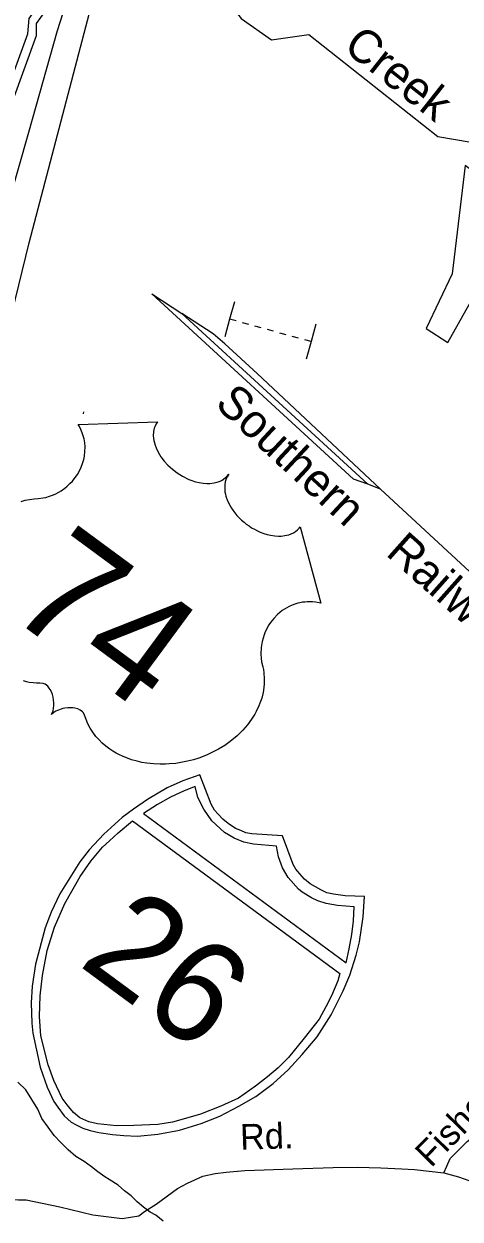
# Model space of a CAD drawing. Extents: x 945666 to 965748, y 644452 to 663300.
# Drawn here: x 952293 to 952548, y 658594 to 659294 of the extents above; entities that cross this region are included whole.
import ezdxf

# ---------------------------------------------------------------- set-up
doc = ezdxf.new("R2010")
doc.units = 0
for name, color, linetype in [('Exist Hydrographic Buffer Line', 7, 'Continuous'), ('Exist Hydrographic Creek Single Shore', 7, 'Continuous'), ('Exist Hydrographic Pond Under 1500 Sq Ft', 7, 'Continuous'), ('Exist Hydrographic River Shore', 7, 'Continuous'), ('Exist Railroad Mainline Label', 7, 'Continuous'), ('Exist Railroad Siding', 7, 'Continuous'), ('Exist Road Primary Interstate Divided Center Attributed', 7, 'Continuous'), ('Exist Road Primary Interstate Shield Number Label', 7, 'Continuous'), ('Exist Road Primary Interstate Structure Vehicle Undrpass CELL', 7, 'Continuous'), ('Exist Road Primary US Shield Number Label', 7, 'Continuous'), ('Exist Road Secondary Type 51 Attributed', 7, 'Continuous'), ('Exist Road Secondary Type 51 Label', 7, 'Continuous'), ('Prop Paved Shoulder', 7, 'Continuous'), ('Prop Shade Light', 7, 'Continuous'), ('Prop Terminator CELL', 7, 'Continuous'), ('Sheet Title CELL', 7, 'Continuous')]:
    doc.layers.add(name, color=color, linetype=linetype)

msp = doc.modelspace()

# ---------------------------------------------------------------- linework, layer by layer
at = {"layer": 'Exist Hydrographic Buffer Line'}
for points in [[(952295, 659288.27), (952295.93, 659297.32), (952305.44, 659310.93), (952312.26, 659335.51)], [(952184.88, 658621.35), (952177.44, 658687.19), (952181.39, 658753.39), (952195.29, 658856.25), (952214.9, 658982.47), (952235.87, 659046.83), (952242.36, 659117.47), (952249.52, 659158.51), (952261.34, 659195.91), (952295, 659288.27)]]:
    msp.add_lwpolyline(points, dxfattribs=at)
at = {"layer": 'Exist Hydrographic Creek Single Shore'}
for points in [[(952332.6, 659363.1), (952363.43, 659340.89), (952391.12, 659328.73), (952405.78, 659315.85), (952420.09, 659297.31), (952437.78, 659284.79), (952459.62, 659287.9), (952535.2, 659228.17), (952554.77, 659224.95), (952566.09, 659226.99)], [(952374.28, 658592.95), (952370.07, 658596.42), (952366.78, 658598.08), (952362.86, 658601.09), (952359.04, 658604.24), (952355.64, 658607.72), (952351.73, 658610.73), (952348.01, 658614.01), (952342.76, 658617.19), (952340.09, 658618.82), (952336.17, 658621.83), (952332.45, 658624.69), (952328.02, 658627.88), (952323.12, 658630.79), (952318.77, 658634.57), (952314.15, 658639.2), (952310.42, 658643.14), (952306.89, 658648), (952303.36, 658653.08), (952300.87, 658658.43), (952297.46, 658664.06), (952293.81, 658669.88), (952289.3, 658674.22)]]:
    msp.add_lwpolyline(points, dxfattribs=at)
at = {"layer": 'Exist Hydrographic Pond Under 1500 Sq Ft'}
msp.add_line((952327.59, 659065.82), (952327.87, 659066.92), dxfattribs=at)
msp.add_lwpolyline([(952541.15, 659107.46), (952561.6, 659143.99), (952563.9, 659201.58), (952551.33, 659211.25), (952543.67, 659147.67), (952528.48, 659115.69), (952541.15, 659107.46)], dxfattribs=at)
at = {"layer": 'Exist Hydrographic River Shore'}
msp.add_lwpolyline([(952190.58, 658617.15), (952182.63, 658686.88), (952186.54, 658752.7), (952200.43, 658855.45), (952219.84, 658980.86), (952240.98, 659045.77), (952247.49, 659116.59), (952254.31, 659156.5), (952268.31, 659189.83), (952266.21, 659194.13), (952300.2, 659287.35), (952300.19, 659294.35), (952310.21, 659308.69), (952320.45, 659345.96), (952321.5, 659348.05)], dxfattribs=at)
at = {"layer": 'Exist Railroad Siding'}
for p, q in [((952494.15, 659024.46), (952385.24, 659124.54)), ((952501.65, 659021.7), (952494.15, 659024.46)), ((952553.83, 658973.41), (952501.65, 659021.7))]:
    msp.add_line(p, q, dxfattribs=at)
for points in [[(952494.15, 659024.46), (952485.83, 659027.41), (952367.75, 659136.05), (952385.24, 659124.54)], [(952501.65, 659021.7), (952429.32, 659089.36), (952410.47, 659106.65), (952403.55, 659112.61), (952385.24, 659124.54)]]:
    msp.add_lwpolyline(points, dxfattribs=at)
at = {"layer": 'Exist Road Primary Interstate Divided Center Attributed'}
for points in [[(952218.29, 658596.72), (952220.44, 658613.7), (952228.12, 658689.95), (952243.24, 658837.53), (952254.14, 658963.62), (952258.26, 658998.75), (952267.23, 659049.19), (952295.78, 659165.98), (952342.48, 659343.91), (952356.23, 659395.14)], [(952336.65, 659368.59), (952330.58, 659347.56), (952312.18, 659290.03), (952295.46, 659230.61), (952272.27, 659149.42), (952256.21, 659087.83), (952244.09, 659032.36), (952239.92, 659005.62), (952235.48, 658965.71), (952215.32, 658767.01), (952200.36, 658609.94)]]:
    msp.add_lwpolyline(points, dxfattribs=at)
at = {"layer": 'Exist Road Primary Interstate Structure Vehicle Undrpass CELL'}
for p, q in [((952416.08, 659131.43), (952413.26, 659121.15)), ((952413.26, 659121.15), (952410.44, 659110.86)), ((952417.06, 659120.13), (952413.27, 659121.17)), ((952424.43, 659118.1), (952420.75, 659119.11)), ((952463.84, 659118.34), (952461.02, 659108.05)), ((952431.8, 659116.08), (952428.12, 659117.09)), ((952439.05, 659114.08), (952435.37, 659115.1)), ((952446.42, 659112.06), (952442.74, 659113.07)), ((952453.65, 659110.08), (952449.96, 659111.09)), ((952461.02, 659108.05), (952457.33, 659109.07)), ((952461.02, 659108.05), (952458.2, 659097.77))]:
    msp.add_line(p, q, dxfattribs=at)
at = {"layer": 'Exist Road Secondary Type 51 Attributed'}
for points in [[(952538.83, 658621.21), (952540.53, 658625.12), (952542.41, 658629.48), (952552.45, 658639.48), (952567.61, 658651.44), (952576.86, 658661.58), (952596.81, 658693.78), (952603.46, 658702.99), (952607.51, 658707.74)], [(952275.84, 658603.72), (952279.85, 658604.75), (952285.32, 658605.57), (952289.63, 658605.42), (952294.06, 658605.45), (952313.72, 658601.29), (952333.2, 658596.51), (952350.33, 658594.35), (952360.18, 658596.03), (952363.5, 658598.46), (952370.22, 658602.9), (952382.74, 658611.93), (952388.68, 658615.08), (952397.67, 658619.16), (952404.81, 658620.73), (952411.3, 658621.63), (952422.18, 658622.6), (952450.3, 658623.54), (952473.93, 658624.39), (952488.27, 658624.44), (952501.8, 658624.19), (952514.12, 658623.5), (952521.65, 658623.11), (952538.83, 658621.21)], [(952538.83, 658621.21), (952547.25, 658618.83), (952553.96, 658616.54), (952557.75, 658614.48), (952564.84, 658609.7), (952567.41, 658605.59), (952571.13, 658600.63), (952575.88, 658591.67), (952578.65, 658582.03), (952580.78, 658565.71), (952581.64, 658556.04), (952582.97, 658542.02), (952586.67, 658491.09), (952588.4, 658469.76), (952591.07, 658427.09), (952591.1, 658412.52), (952591.14, 658406.64), (952591.15, 658399.33), (952590.7, 658391.2), (952589.55, 658376.03), (952585.63, 658355.48), (952576.67, 658332.4)]]:
    msp.add_lwpolyline(points, dxfattribs=at)
at = {"layer": 'Prop Shade Light'}
for points in [[(952320.52, 658650.86), (952323.31, 658649.2), (952327.31, 658647.29), (952331.54, 658645.9), (952336.68, 658644.76), (952344.75, 658643.71), (952351.34, 658643.01), (952359.29, 658642.66), (952371.27, 658643.88), (952383.99, 658646.14), (952396.6, 658650.01), (952407.5, 658654.28), (952418.63, 658660.13), (952428.59, 658665.91), (952438.68, 658673.45), (952447.56, 658681.43), (952455.78, 658690.52), (952464.45, 658700.91), (952472.74, 658713.7), (952479.85, 658727.79), (952483.6, 658737.05), (952487.44, 658748.62), (952489.37, 658756.4), (952491.43, 658771.18), (952492.28, 658783.12), (952480.91, 658783.37), (952474.12, 658784.38), (952470.15, 658785.23), (952466.64, 658786.9), (952460.5, 658790.37), (952457.08, 658793.14), (952454.34, 658796.3), (952452.01, 658798.96), (952450.56, 658801.75), (952444.21, 658818.57), (952426.24, 658819.69), (952422.82, 658820.39), (952419.81, 658821.77), (952416.78, 658822.93), (952412.47, 658825.79), (952409.36, 658828.24), (952406.53, 658831.23), (952404.35, 658833.67), (952402.49, 658837.2), (952395.89, 658854.2), (952385.81, 658850.73), (952376.68, 658846.68), (952365.18, 658839.92), (952356.92, 658834.2), (952350.41, 658829.3), (952339.61, 658819.46), (952331.02, 658810.29), (952325.57, 658803.34), (952313.8, 658784.65), (952308.77, 658773.78), (952305.13, 658764.68), (952299.52, 658743.34), (952297.63, 658730.46), (952296.97, 658720.7), (952297.39, 658708.86), (952297.98, 658702.93), (952302.35, 658683.08), (952306.44, 658671.4), (952310.39, 658663.01), (952312.61, 658659.56), (952316.45, 658654.65)], [(952393.16, 658847.41), (952386.71, 658844.99), (952378.6, 658841.28), (952371.01, 658836.83), (952362.87, 658831.74), (952481.44, 658744.23), (952483.22, 658752.43), (952484.83, 658760.8), (952485.9, 658768.73), (952486.17, 658776.98), (952476.43, 658777.7), (952469.9, 658778.98), (952465.01, 658780.51), (952461.17, 658782.2), (952455.76, 658785.56), (952453.57, 658787.38), (952447.64, 658794.25), (952444.27, 658799.78), (952441.93, 658806.23), (952440.8, 658812.47), (952427.21, 658813.71), (952421.69, 658814.95), (952415.99, 658817.26), (952410.26, 658820.47), (952402.82, 658827.31), (952398.09, 658834.18), (952394.72, 658841.05)], [(952477.82, 658737.86), (952476.62, 658733.57), (952472.89, 658724.85), (952469.58, 658718.45), (952465.66, 658711.16), (952457, 658700.1), (952447.82, 658688.8), (952441.63, 658682.66), (952435.55, 658677.42), (952428.42, 658671.87), (952418.39, 658664.91), (952408.21, 658660.27), (952396.3, 658655.55), (952384.75, 658652.24), (952379.84, 658650.95), (952371.19, 658649.41), (952357.09, 658648.83), (952347.06, 658648.77), (952335.95, 658649.91), (952330.73, 658651.06), (952325.44, 658653.48), (952321.87, 658656.52), (952318.19, 658661.1), (952315.24, 658664.84), (952310.38, 658675.18), (952307.05, 658684.39), (952302.73, 658701.42), (952301.93, 658712.67), (952302.37, 658724.81), (952303.57, 658736.7), (952306.36, 658751.47), (952310.75, 658765.16), (952316.8, 658778.99), (952325.65, 658794.79), (952331.95, 658803.75), (952338.74, 658811.83), (952342.82, 658815.68), (952347.96, 658820.4), (952356.4, 658827.32)]]:
    msp.add_lwpolyline(points, close=True, dxfattribs=at)
at = {"layer": 'Prop Terminator CELL'}
msp.add_lwpolyline([(952291.22, 659014.48), (952293.44, 659015.1), (952296.13, 659015.63), (952298.78, 659015.97), (952301.05, 659016.07), (952303.97, 659016.48), (952305.58, 659016.83), (952307.68, 659017.45), (952309.47, 659018.12), (952311, 659018.78), (952313.15, 659019.83), (952314.63, 659020.72), (952316.75, 659022.19), (952318.1, 659023.32), (952319.76, 659024.84), (952321.22, 659026.35), (952322.85, 659028.38), (952324.07, 659030.14), (952325.33, 659032.33), (952326.38, 659034.54), (952327.17, 659036.57), (952327.87, 659039.04), (952328.25, 659040.94), (952328.54, 659043.68), (952328.61, 659046.38), (952328.39, 659048.77), (952328.05, 659051.02), (952327.53, 659052.91), (952326.97, 659054.62), (952326.15, 659056.61), (952325.24, 659058.38), (952324.6, 659059.4), (952370.97, 659061.13), (952370.15, 659059.86), (952369.39, 659058.22), (952369.07, 659057.31), (952368.69, 659055.4), (952368.56, 659052.91), (952368.9, 659050.13), (952369.58, 659047.41), (952370.2, 659045.79), (952371.4, 659043.25), (952372.96, 659040.63), (952374.94, 659038.05), (952377.13, 659035.64), (952379.72, 659033.25), (952382.45, 659031.15), (952385.62, 659029.16), (952389.4, 659027.36), (952391.23, 659026.62), (952393.37, 659025.95), (952395.44, 659025.44), (952397.87, 659025.08), (952399.93, 659024.95), (952401.61, 659024.94), (952404.26, 659025.28), (952406.63, 659025.9), (952407.78, 659026.38), (952408.84, 659026.88), (952410.75, 659028.19), (952411.5, 659028.84), (952412.81, 659030.37), (952411.91, 659028.93), (952411.43, 659027.99), (952411.04, 659026.99), (952410.73, 659025.86), (952410.44, 659024.16), (952410.37, 659022.61), (952410.53, 659020.12), (952410.79, 659018.76), (952411.08, 659017.61), (952412.06, 659014.78), (952413.51, 659011.9), (952414.28, 659010.56), (952415.15, 659009.28), (952416.3, 659007.73), (952417.57, 659006.24), (952418.9, 659004.86), (952420.29, 659003.49), (952421.78, 659002.2), (952423.05, 659001.21), (952424.65, 659000.06), (952426.18, 658999.06), (952427.81, 658998.13), (952429.67, 658997.18), (952431.21, 658996.5), (952433.32, 658995.67), (952435.32, 658995.07), (952437.17, 658994.64), (952439.68, 658994.25), (952441.82, 658994.09), (952443.53, 658994.16), (952445.67, 658994.39), (952447.91, 658994.9), (952449.36, 658995.4), (952450.64, 658996.08), (952451.92, 658996.84), (952453.07, 658997.81), (952453.96, 658998.72), (952454.63, 658999.57), (952466.68, 658954.76), (952465.79, 658955.01), (952463.64, 658955.4), (952461.83, 658955.59), (952458.78, 658955.65), (952457.34, 658955.51), (952455.88, 658955.34), (952454.45, 658955.06), (952453.15, 658954.76), (952451.44, 658954.21), (952449.82, 658953.6), (952448.12, 658952.85), (952446.75, 658952.13), (952444.12, 658950.45), (952442.6, 658949.28), (952441.39, 658948.22), (952439.12, 658945.87), (952438.12, 658944.69), (952437.22, 658943.47), (952436.33, 658942.12), (952435.54, 658940.79), (952434.81, 658939.33), (952434.17, 658938.04), (952433.5, 658936.37), (952432.82, 658934.37), (952432.3, 658932.33), (952431.77, 658928.81), (952431.58, 658924.95), (952431.73, 658922.6), (952432.02, 658920.47), (952432.71, 658917.62), (952433.04, 658916.04), (952433.34, 658914.09), (952433.6, 658910.62), (952433.6, 658909.07), (952433.53, 658907.39), (952433.37, 658905.73), (952433.14, 658903.98), (952432.89, 658902.48), (952432.07, 658899.22), (952431.03, 658896.24), (952430.43, 658894.7), (952428.86, 658891.44), (952428.02, 658889.87), (952426.18, 658886.91), (952423.7, 658883.52), (952421.07, 658880.5), (952417.71, 658877.2), (952415.55, 658875.33), (952412.86, 658873.29), (952410.45, 658871.57), (952406.66, 658869.23), (952403.7, 658867.68), (952400.07, 658865.98), (952397.76, 658865.05), (952395.19, 658864.13), (952392.1, 658863.15), (952388.65, 658862.23), (952384.75, 658861.46), (952381.72, 658861), (952377.94, 658860.64), (952375.72, 658860.52), (952372.66, 658860.49), (952368.65, 658860.68), (952364.86, 658861.1), (952361.75, 658861.61), (952359.11, 658862.22), (952355.8, 658863.15), (952350.61, 658865.14), (952348.79, 658865.97), (952346.73, 658867.06), (952344.86, 658868.18), (952343.09, 658869.32), (952340.81, 658871), (952338.68, 658872.84), (952336.77, 658874.73), (952334.89, 658876.83), (952333.07, 658879.24), (952331.57, 658881.63), (952330.21, 658884.26), (952328.27, 658889.2), (952327.64, 658890.52), (952327.16, 658891.11), (952325.82, 658892.21), (952324.3, 658892.9), (952322.56, 658893.36), (952321.43, 658893.52), (952319.83, 658893.61), (952318.52, 658893.57), (952316.82, 658893.36), (952315.55, 658893.07), (952314.56, 658892.84), (952312.36, 658891.98), (952311.44, 658891.49), (952310.33, 658890.79), (952308.93, 658889.58), (952309.82, 658891.75), (952310.18, 658893.35), (952310.32, 658894.85), (952310.35, 658896.24), (952310.19, 658898.16), (952309.93, 658899.72), (952309.49, 658901.43), (952308.84, 658903), (952308.25, 658904.18), (952307.63, 658905.14), (952306.77, 658906.18), (952305.96, 658906.88), (952305.24, 658907.39), (952304.1, 658907.88), (952302.08, 658907.91), (952300.19, 658907.97), (952298.2, 658908.12), (952295.95, 658908.46), (952294.35, 658908.78), (952292.53, 658909.27)], dxfattribs=at)

# ---------------------------------------------------------------- texts
at = {"layer": 'Exist Railroad Mainline Label'}
for s, rotation, p in [('Southern', 317.06053, (952403.98, 659070.74)), ('Railway', 318.4103, (952504.12, 658983.37))]:
    msp.add_text(s, height=19.486, rotation=rotation, dxfattribs=at).set_placement(p)
at = {"layer": 'Exist Road Primary Interstate Shield Number Label'}
msp.add_text('26', height=59.759, rotation=323.59084, dxfattribs=at).set_placement((952323.87, 658743.35))
at = {"layer": 'Exist Road Primary US Shield Number Label'}
msp.add_text('74', height=66.589, rotation=323.59084, dxfattribs=at).set_placement((952281.39, 658949.52))
at = {"layer": 'Exist Road Secondary Type 51 Label'}
for s, rotation, p in [('Fisher', 45.62405, (952531.31, 658623.76)), ('Rd.', 1.95044, (952419.64, 658634.62))]:
    msp.add_text(s, height=15, rotation=rotation, dxfattribs=at).set_placement(p)
at = {"layer": 'Prop Paved Shoulder'}
msp.add_text('Creek', height=19.486, rotation=321.68143, dxfattribs=at).set_placement((952479.1, 659279.25))
at = {"layer": 'Sheet Title CELL'}
msp.add_text('TIP PROJECT:', height=249.9998, rotation=53.59084, dxfattribs=at).set_placement((951327.58, 658659.91))

doc.saveas('drawing.dxf')
